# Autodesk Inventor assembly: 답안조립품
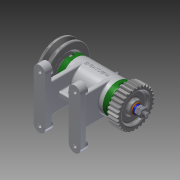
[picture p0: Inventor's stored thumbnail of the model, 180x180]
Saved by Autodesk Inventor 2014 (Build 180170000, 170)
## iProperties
Created: 2015-11
Part Number: 답안조립품
Document SubType Name: Assembly
Designer: test_26
Author: test_26
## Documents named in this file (16)
- C:\Users\test_26\Desktop\김효섭\답안조립품.iam
- C:\Users\test_26\Desktop\김효섭\1-본체.ipt
- C:\Users\test_26\Desktop\김효섭\451109V1040\V벨트풀리.ipt
- C:\Users\test_26\Desktop\김효섭\451109V1040\너트 M 8.ipt
- C:\Users\test_26\Desktop\김효섭\451109V1040\니플 M 6 x 0.75.ipt
- C:\Users\test_26\Desktop\김효섭\451109V1040\베어링 15 x 32 x 9.ipt
- C:\Users\test_26\Desktop\김효섭\451109V1040\볼트 M 6 x 8.ipt
- C:\Users\test_26\Desktop\김효섭\451109V1040\볼트 M4 x 12.ipt
- C:\Users\test_26\Desktop\김효섭\451109V1040\스퍼기어.ipt
- C:\Users\test_26\Desktop\김효섭\451109V1040\스프링와셔 8.ipt
- C:\Users\test_26\Desktop\김효섭\451109V1040\오일 실 15 25 7.ipt
- C:\Users\test_26\Desktop\김효섭\451109V1040\와셔 6x11.5.ipt
- C:\Users\test_26\Desktop\김효섭\451109V1040\와셔 8x17.ipt
- C:\Users\test_26\Desktop\김효섭\451109V1040\축.ipt
- C:\Users\test_26\Desktop\김효섭\451109V1040\커버.ipt
- C:\Users\test_26\Desktop\김효섭\451109V1040\키 3 x 3 x 12.ipt
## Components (12 placed, 4 different names)
1. 1-본체:1
2. V벨트풀리:1
3. KS B 2023 6002 - 15 x 32 x 9:1
4. KS B 2023 6002 - 15 x 32 x 9:2
5. ISO 4762 M4 x 12:2
6. ISO 4762 M4 x 12:3
7. ISO 4762 M4 x 12:4
8. ISO 4762 M4 x 12:5
9. ISO 4762 M4 x 12:6
10. ISO 4762 M4 x 12:7
11. ISO 4762 M4 x 12:8
12. ISO 4762 M4 x 12:9
